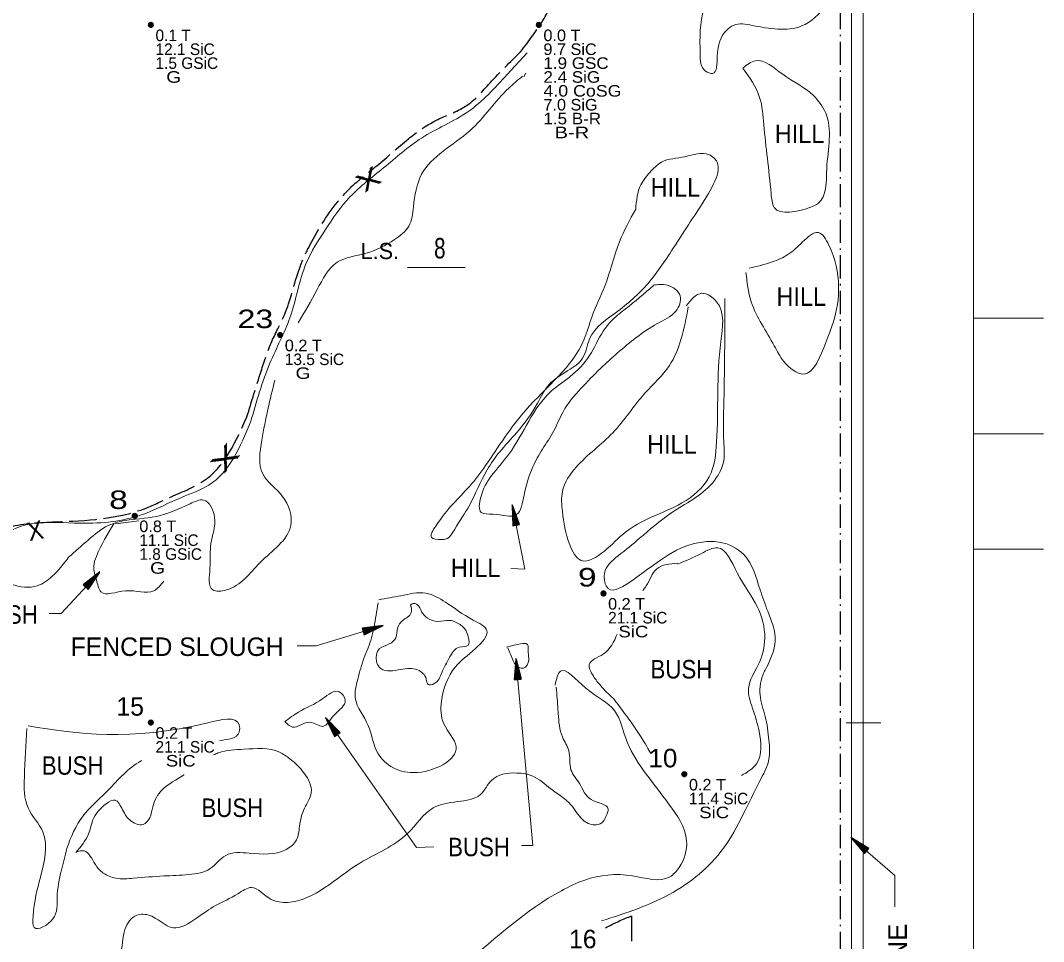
# Model space of a CAD drawing. Extents: x -496 to 480, y -450 to 700.
# Drawn here: x 37.7 to 480.3, y -94.7 to 303.7 of the extents above; entities that cross this region are included whole.
import ezdxf
from ezdxf.enums import TextEntityAlignment as Align

# ---------------------------------------------------------------- set-up
doc = ezdxf.new("R2010")
doc.units = 0
doc.header["$LTSCALE"] = 2
doc.linetypes.add('DOT_DASHED', pattern=[7.7, 5, -1.2, 0.3, -1.2])
doc.linetypes.add('LONG_DASHED', pattern=[7.5, 6, -1.5])
for name, color, linetype, lineweight in [('1', 7, 'Continuous', 13), ('2', 7, 'Continuous', 35), ('3', 7, 'Continuous', 13), ('4', 7, 'Continuous', 25)]:
    doc.layers.add(name, color=color, linetype=linetype, lineweight=lineweight)

msp = doc.modelspace()

# ---------------------------------------------------------------- linework, layer by layer
at = {"layer": '1'}
for p, q in [((205.122, 196.887), (230.122, 196.887)), ((480.331, 174.973), (449.983, 174.973)), ((480.331, 124.973), (449.983, 124.973)), ((480.331, 74.973), (449.983, 74.973)), ((394.983, -0.027), (409.983, -0.027))]:
    msp.add_line(p, q, dxfattribs=at)
for points in [[(449.983, -450.027), (449.983, 399.973), (449.983, 699.973), (-450.017, 699.973), (-450.017, 49.973), (-450.017, -450.027)], [(402.281, -402.333), (402.281, 402.339), (-402.391, 402.339)]]:
    msp.add_lwpolyline(points, dxfattribs=at)
at = {"layer": '2', "linetype": 'LONG_DASHED', "lineweight": 25}
msp.add_line((302.281, -94.495), (302.281, -83.522), dxfattribs=at)
at = {"layer": '2'}
for centre in [(94.135, 301.781), (261.975, 301.781), (150.082, 167.664), (87.142, 89.429), (289.948, 55.9), (94.135, 0.018), (324.915, -22.335)]:
    msp.add_circle(centre, 1, dxfattribs=at)
at = {"layer": '2', "linetype": 'LONG_DASHED', "lineweight": 25}
for points in [[(254.05, 290.114), (264.26, 304.622), (270.894, 317.609), (281.508, 339.607), (287.876, 356.304), (287.345, 399.506)], [(135.71, 132.34), (141.814, 151.978), (146.458, 164.864), (152.392, 177.492), (158.843, 197.594), (162.455, 205.583), (174.84, 225.169), (181.29, 232.128), (191.869, 240.89), (205.543, 252.487), (217.412, 260.477), (230.313, 266.662), (240.891, 276.713), (254.05, 290.114)], [(-121.657, 20.504), (-107.33, 29.42), (-86.423, 39.115), (-52.45, 53.658), (-20.343, 66.337), (-7.277, 69.693), (3.177, 71.184), (11.763, 72.676), (19.23, 74.913), (25.95, 80.134), (29.31, 83.117), (33.043, 84.609), (52.83, 86.846), (92.03, 92.813), (102.856, 97.66), (117.79, 105.118), (135.71, 132.34)], [(290.885, -88.682), (301.552, -83.811), (302.246, -83.558)]]:
    msp.add_spline(points, degree=3, dxfattribs=at)
at = {"layer": '2'}
for points in [[(94.124, 302.668), (94.855, 302.263), (95.006, 301.415), (94.321, 300.887), (93.512, 301.117), (93.226, 301.876), (93.473, 302.437), (94.046, 302.606), (94.72, 302.112), (94.703, 301.37), (94.186, 301.112), (93.664, 301.28), (93.439, 301.926), (94.023, 302.392), (94.461, 301.859), (94.422, 301.376), (93.793, 301.511), (93.939, 302.145), (94.231, 301.595)], [(261.964, 302.668), (262.694, 302.263), (262.846, 301.415), (262.161, 300.887), (261.352, 301.117), (261.065, 301.876), (261.313, 302.437), (261.886, 302.606), (262.56, 302.112), (262.543, 301.37), (262.026, 301.112), (261.504, 301.28), (261.279, 301.926), (261.863, 302.392), (262.301, 301.859), (262.262, 301.376), (261.633, 301.511), (261.779, 302.145), (262.071, 301.595)], [(150.071, 168.551), (150.801, 168.146), (150.953, 167.298), (150.268, 166.77), (149.459, 167), (149.172, 167.759), (149.419, 168.32), (149.992, 168.489), (150.666, 167.995), (150.65, 167.253), (150.133, 166.995), (149.61, 167.163), (149.386, 167.809), (149.97, 168.275), (150.408, 167.742), (150.369, 167.259), (149.74, 167.394), (149.886, 168.028), (150.178, 167.478)], [(87.131, 90.316), (87.861, 89.911), (88.013, 89.063), (87.328, 88.535), (86.519, 88.766), (86.232, 89.524), (86.479, 90.085), (87.052, 90.254), (87.726, 89.76), (87.71, 89.018), (87.193, 88.76), (86.67, 88.928), (86.446, 89.574), (87.03, 90.041), (87.468, 89.507), (87.429, 89.024), (86.8, 89.159), (86.946, 89.793), (87.238, 89.243)], [(289.937, 56.787), (290.668, 56.382), (290.819, 55.534), (290.134, 55.006), (289.325, 55.236), (289.039, 55.995), (289.286, 56.556), (289.859, 56.725), (290.533, 56.231), (290.516, 55.489), (289.999, 55.231), (289.477, 55.399), (289.252, 56.045), (289.836, 56.511), (290.274, 55.978), (290.235, 55.495), (289.606, 55.63), (289.752, 56.264), (290.044, 55.714)], [(94.124, 0.905), (94.855, 0.5), (95.006, -0.348), (94.321, -0.876), (93.512, -0.646), (93.226, 0.113), (93.473, 0.674), (94.046, 0.843), (94.72, 0.349), (94.703, -0.393), (94.186, -0.651), (93.664, -0.483), (93.439, 0.163), (94.023, 0.629), (94.461, 0.096), (94.422, -0.387), (93.793, -0.252), (93.939, 0.382), (94.231, -0.168)], [(324.904, -21.448), (325.634, -21.853), (325.786, -22.701), (325.101, -23.229), (324.292, -22.998), (324.005, -22.24), (324.253, -21.679), (324.826, -21.51), (325.5, -22.004), (325.483, -22.746), (324.966, -23.004), (324.444, -22.836), (324.219, -22.19), (324.803, -21.723), (325.241, -22.257), (325.202, -22.74), (324.573, -22.605), (324.719, -21.971), (325.011, -22.521)]]:
    msp.add_spline(points, degree=3, dxfattribs=at)
at = {"layer": '3', "linetype": 'DOT_DASHED', "lineweight": 25}
msp.add_line((392.281, 402.339), (392.281, -396.11), dxfattribs=at)
at = {"layer": '3'}
for p, q in [((397.281, -401.02), (397.281, 402.339)), ((248.211, 280.36), (256.977, 289.788)), ((255.491, 279.414), (256.384, 280.86)), ((78.844, 86.069), (88.946, 87.27))]:
    msp.add_line(p, q, dxfattribs=at)
for points in [[(383.644, 368.574), (387.241, 361.902), (386.213, 310.321), (375.679, 301.339), (354.355, 301.595), (346.133, 301.595), (343.307, 299.542), (339.196, 288.251), (337.141, 280.809), (334.058, 281.835), (331.746, 289.277), (333.287, 308.781), (339.453, 323.408), (346.647, 337.523), (355.383, 351.894), (368.486, 365.238), (373.367, 368.318), (382.873, 368.831)], [(350.236, 283.16), (355.682, 286.333), (367.481, 280.441), (380.642, 271.375), (386.088, 263.669), (386.541, 239.644), (382.911, 224.686), (379.28, 222.873), (363.85, 222.873), (362.489, 228.765), (359.312, 258.683), (357.497, 270.468), (350.236, 283.16)], [(137.427, 130.372), (145.648, 155.543), (154.293, 175.168), (161.366, 198.719), (169.619, 213.241), (180.229, 227.372), (194.768, 239.932), (211.273, 252.885), (231.314, 264.268), (248.211, 280.36)], [(157.893, 172.939), (166.082, 187.336), (174.727, 199.111), (187.302, 203.036), (199.484, 208.924), (205.771, 214.811), (207.736, 223.054), (211.273, 237.184), (232.1, 256.025), (248.997, 274.473), (254.892, 279.575)], [(303.887, 222.042), (306.119, 232.62), (309.971, 237.963), (315.107, 242.452), (325.164, 244.803), (335.65, 245.658), (339.074, 242.452), (337.576, 233.047), (328.374, 217.871), (321.526, 207.398)], [(321.469, 207.29), (309.982, 190.899), (296.151, 178.02), (283.96, 166.078), (280.913, 157.649), (274.583, 152.263), (266.378, 146.175), (261.455, 138.214), (252.313, 125.335), (245.045, 117.14), (239.654, 109.413), (231.918, 93.959), (225.588, 83.656), (221.837, 79.441), (219.962, 79.207), (215.508, 80.143), (217.383, 85.061), (224.885, 94.661), (231.918, 102.154), (238.95, 111.286), (256.298, 135.17), (281.616, 165.844), (284.898, 175.445), (290.524, 188.792), (296.854, 207.992), (303.887, 222.042)], [(352.959, 196.582), (362.943, 199.301), (369.75, 202.474), (376.104, 207.914), (382.911, 211.994), (387.449, 206.554), (389.264, 173.01), (386.088, 164.398), (376.557, 150.799), (367.935, 156.239), (363.85, 163.038), (353.866, 182.076), (351.597, 194.768)], [(311.388, 189.26), (317.484, 189.26), (323.11, 184.577), (321.234, 178.02), (313.264, 172.635), (304.121, 166.547), (288.649, 153.2), (280.21, 144.536), (272.473, 134.467), (268.488, 126.272), (263.565, 118.311), (259.346, 110.584), (255.595, 98.407), (252.313, 89.978), (242.232, 90.212), (237.075, 90.915), (236.841, 97.471), (241.529, 106.837), (249.031, 116.203), (267.316, 143.365), (275.521, 149.688), (283.96, 158.82), (289.821, 169.357), (296.151, 176.381), (299.433, 178.957), (311.623, 189.026)], [(325.73, 180.263), (332.537, 185.703), (338.89, 182.076), (340.706, 164.851), (338.89, 121.335), (335.714, 106.376), (323.914, 95.044), (310.3, 88.698), (299.408, 82.352), (290.332, 74.193), (280.348, 70.113), (275.356, 76.912), (272.179, 91.418), (272.179, 100.03), (278.079, 110.456), (293.962, 125.415), (308.031, 142.64), (318.469, 154.425), (323.461, 165.758), (326.637, 179.81)], [(342.51, 183.423), (341.967, 136.203), (341.967, 121.549), (341.967, 113.407), (337.076, 103.637), (319.145, 90.611), (305.56, 79.756), (296.322, 72.157), (290.345, 64.559), (291.975, 58.045), (302.843, 61.845), (332.729, 78.128), (339.793, 78.128), (350.661, 72.7), (357.725, 57.503), (360.986, 48.276), (364.246, 35.249), (360.442, 23.851), (359.355, 21.68), (357.725, 11.911), (359.899, 2.684), (361.529, -7.629), (361.529, -15.77), (358.269, -23.912), (351.205, -38.023), (343.054, -52.678), (320.231, -73.303), (289.162, -85.708)], [(58.543, 71.571), (67.055, 79.004), (75.7, 85.284), (81.988, 87.246), (96.527, 89.209), (111.067, 94.704), (116.961, 96.274), (121.677, 88.816), (120.105, 77.434), (119.712, 66.836), (120.891, 57.416), (126.786, 57.416), (141.325, 69.191), (154.686, 85.284), (151.149, 97.844), (142.504, 107.657), (142.111, 122.179), (147.765, 148.125)], [(-282.859, -78.008), (-272.887, -80.134), (-264.057, -83.662), (-249.928, -81.31), (-235.8, -71.902), (-185.173, -32.505), (-142.788, 2.187), (-109.233, 24.531), (-88.629, 34.527), (-62.138, 46.287), (-34.47, 58.047), (-7.39, 66.867), (13.803, 69.807), (24.988, 75.099), (30.874, 80.979), (65.607, 86.271), (91.509, 90.387), (107.404, 97.443), (119.177, 102.736), (137.427, 130.372)], [(99.777, 61.259), (95.348, 57.023), (83.167, 57.023), (72.557, 56.631), (70.592, 61.733), (69.413, 67.621), (70.592, 71.938), (78.058, 86.069)], [(322.126, 68.618), (332.319, 73.182), (339.349, 75.64), (347.784, 64.756), (356.572, 50.011), (359.735, 36.67), (356.923, 25.084), (352.705, 14.903), (354.463, 6.126), (357.274, -3.705), (356.22, -17.748), (349.646, -22.911)], [(-18.491, 54.826), (-14.454, 56.283), (6.738, 63.927), (20.867, 64.515), (33.818, 59.811), (45.003, 59.223), (51.478, 63.339), (58.543, 71.571)], [(307.006, 57.211), (308.418, 59.139), (312.987, 66.512), (322.126, 68.969)], [(192.778, 53.171), (202.268, 54.926), (213.164, 55.979), (221.6, 52.117), (233.55, 44.393), (239.526, 39.829), (234.605, 32.106), (225.818, 24.031), (219.842, 9.285), (220.897, -0.545), (226.169, -10.375), (207.892, -21.61), (191.723, -12.131), (188.208, -1.247), (182.584, 10.69), (183.639, 18.765), (186.451, 28.244), (189.614, 36.67), (190.669, 41.234), (192.426, 51.766)], [(206.316, 50.903), (208.035, 51.546), (209.431, 51.01), (211.257, 48.006), (213.835, 45.216), (218.346, 43.822), (223.287, 44.251), (226.831, 43.071), (230.376, 39.96), (231.45, 37.063), (231.45, 33.415), (227.583, 32.664), (223.394, 28.265), (219.957, 21.614), (216.735, 16.893), (214.05, 16.571), (213.298, 18.824), (209.538, 22.794), (202.235, 23.009), (193.642, 23.438), (191.923, 25.905), (193.105, 32.02), (197.294, 34.059), (200.086, 36.741), (200.838, 40.925), (204.168, 45.002), (206.101, 46.504), (206.961, 48.971), (206.531, 50.688)], [(294.358, 10.339), (288.734, 15.956), (285.571, 20.169), (283.813, 25.084), (289.789, 29.648), (295.888, 38.272)], [(247.989, 32.662), (252.68, 33.834), (257.077, 33.834), (257.37, 30.32), (257.663, 27.099), (255.318, 23.585), (251.507, 25.635), (250.921, 26.806), (248.575, 32.369)], [(269.001, 16.283), (271.297, 22.245), (282.315, 14.908), (294.71, 5.278), (300.22, -8.479), (308.483, -22.236), (318.124, -35.075), (325.929, -51.125), (322.715, -62.589), (318.583, -66.716), (302.515, -66.257), (281.856, -68.092), (271.756, -72.677), (229.979, -104.318), (217.583, -115.323), (209.319, -124.036), (201.974, -129.997), (187.283, -135.5), (173.51, -135.5), (164.787, -144.671), (158.36, -152.467), (154.228, -151.55), (144.587, -147.423), (132.192, -141.92), (117.042, -145.588), (110.615, -162.096), (118.878, -177.688), (120.715, -195.571), (117.96, -205.201), (111.992, -218.499), (104.646, -223.085), (95.006, -224.002), (82.61, -230.422), (72.051, -234.549), (59.196, -234.09), (48.637, -233.173), (45.883, -229.046), (46.801, -175.395), (47.26, -167.599), (55.524, -158.887), (66.542, -139.627), (70.674, -112.572), (80.315, -102.025), (82.61, -90.561), (87.201, -83.683), (93.169, -83.224), (103.728, -88.727), (113.828, -84.6), (122.092, -79.097), (131.733, -74.053), (137.701, -71.302), (145.965, -76.346), (153.31, -77.721), (184.528, -60.755), (205.188, -47.915), (216.206, -36.91), (226.765, -34.158), (236.865, -30.948), (241.456, -24.987), (252.474, -21.777), (259.36, -23.153), (267.165, -28.655), (275.888, -35.534), (280.938, -41.954), (285.988, -44.247), (289.201, -43.329), (291.038, -40.578), (291.956, -37.368), (284.61, -33.241), (279.56, -26.363), (275.888, -20.401), (274.97, -12.147), (272.215, -6.186), (270.379, 3.902), (269.92, 10.322), (269.46, 15.366)], [(152.127, 0.453), (157.99, 4.552), (168.544, 10.408), (175.58, 13.336), (178.218, 9.823), (173.234, 3.088), (168.544, -1.597), (162.974, 0.16), (155.352, -1.89), (152.127, 0.453)], [(310.473, -13.38), (308.769, -10.375), (294.358, 10.339)], [(41.026, -1.427), (118.712, -0.094), (132.327, -0.894), (132.327, -4.094), (123.81, -7.676)], [(90.271, -16.334), (88.813, -17.16), (74.664, -30.226), (64.786, -40.359), (57.845, -54.491), (55.442, -63.824), (53.573, -75.557), (51.705, -84.89), (43.696, -88.623), (43.162, -83.823), (46.366, -66.758), (47.433, -47.292), (41.026, -36.892), (39.424, -23.56), (40.492, -2.494)], [(121.24, -13.922), (123.32, -13.099), (134.487, -11.505), (149.803, -12.78), (154.27, -15.648), (160.332, -21.704), (163.523, -30.308), (160.651, -37.001), (158.418, -44.969), (157.141, -50.705), (152.674, -54.849), (136.721, -56.442), (126.51, -57.398), (119.81, -63.135), (110.557, -65.684), (99.708, -66.322), (86.627, -67.278), (78.969, -67.278), (73.545, -65.047), (70.035, -61.223), (65.249, -55.486), (62.058, -55.805)], [(61.739, -56.123), (67.163, -48.156), (69.078, -42.1), (74.821, -35.089), (78.65, -33.496), (81.521, -37.001), (85.031, -42.1), (90.774, -44.013), (93.646, -41.144), (94.922, -36.364), (99.07, -29.034), (108.323, -22.66), (108.513, -22.526)]]:
    msp.add_spline(points, degree=3, dxfattribs=at)
at = {"layer": '4', "lineweight": 13}
for points in [[(249.839, 66.649), (255.945, 66.328), (250.482, 94.256)], [(50.16, 47.27), (55.264, 47.27), (72.123, 65.19)], [(157.404, 33.248), (165.612, 33.248), (194.635, 42.032)], [(254.438, -53.133), (259.422, -53.133), (252.093, 27.684)], [(216.621, -53.718), (208.999, -54.011), (169.716, 2.209)], [(416.06, -79.63), (416.06, -66.1), (397.011, -49.61)]]:
    msp.add_lwpolyline(points, dxfattribs=at)
at = {"layer": '4'}
for points in [[(250.482, 94.256), (250.738, 85.136), (253.682, 85.712)], [(72.123, 65.19), (64.863, 59.662), (67.048, 57.607)], [(194.635, 42.032), (185.586, 40.861), (186.455, 37.989)], [(252.093, 27.684), (251.412, 18.586), (254.4, 18.857)], [(169.716, 2.209), (173.642, -6.027), (176.101, -4.309)], [(397.011, -49.61), (402.834, -56.634), (404.797, -54.366)]]:
    msp.add_lwpolyline(points, close=True, dxfattribs=at)
for points in [[(250.811, 85.225), (250.564, 93.834), (253.538, 85.808), (250.932, 85.282), (250.67, 93.292), (253.383, 85.927), (251.018, 85.43), (250.782, 92.719), (253.195, 86.038), (251.158, 85.557), (250.894, 92.065), (253.017, 86.186), (251.287, 85.748), (251.03, 91.281), (252.798, 86.292), (251.447, 85.944), (251.179, 90.436), (252.52, 86.451), (251.584, 86.169), (251.312, 89.502), (252.279, 86.668), (251.728, 86.445), (251.542, 88.407), (251.954, 86.902)], [(64.978, 59.655), (71.827, 64.877), (67.042, 57.78), (65.096, 59.59), (71.449, 64.474), (67.049, 57.974), (65.266, 59.606), (71.049, 64.049), (67.03, 58.193), (65.45, 59.566), (70.583, 63.577), (67.046, 58.423), (65.681, 59.573), (70.025, 63.009), (67.004, 58.663), (65.934, 59.558), (69.426, 62.395), (66.971, 58.982), (66.196, 59.578), (68.745, 61.742), (67.007, 59.304), (66.504, 59.622), (67.99, 60.917), (67.007, 59.705)], [(185.682, 40.797), (194.223, 41.908), (186.536, 38.143), (185.752, 40.682), (193.694, 41.748), (186.639, 38.308), (185.907, 40.611), (193.135, 41.579), (186.731, 38.507), (186.047, 40.485), (192.496, 41.402), (186.86, 38.698), (186.251, 40.376), (191.729, 41.188), (186.944, 38.927), (186.462, 40.236), (190.903, 40.955), (187.074, 39.22), (186.699, 40.123), (189.988, 40.728), (187.265, 39.481), (186.988, 40.007), (188.922, 40.389), (187.465, 39.829)], [(251.494, 18.667), (252.131, 27.256), (254.266, 18.967), (251.621, 18.712), (252.181, 26.706), (254.125, 19.101), (251.722, 18.85), (252.234, 26.124), (253.949, 19.231), (251.874, 18.961), (252.278, 25.462), (253.788, 19.397), (252.022, 19.139), (252.333, 24.668), (253.581, 19.524), (252.201, 19.317), (252.395, 23.812), (253.32, 19.711), (252.36, 19.527), (252.431, 22.87), (253.102, 19.952), (252.531, 19.787), (252.548, 21.757), (252.803, 20.218)], [(173.672, -5.916), (169.962, 1.856), (175.93, -4.279), (173.76, -5.814), (170.279, 1.403), (175.741, -4.233), (173.779, -5.645), (170.613, 0.925), (175.524, -4.207), (173.856, -5.472), (170.98, 0.372), (175.301, -4.144), (173.896, -5.245), (171.422, -0.29), (175.058, -4.136), (173.963, -5.001), (171.9, -1.002), (174.739, -4.103), (173.997, -4.74), (172.4, -1.802), (174.431, -4.002), (174.017, -4.429), (173.053, -2.71), (174.039, -3.92)], [(402.836, -56.519), (397.336, -49.892), (404.624, -54.379), (402.897, -56.399), (397.753, -50.253), (404.43, -54.381), (402.873, -56.23), (398.195, -50.635), (404.213, -54.409), (402.905, -56.044), (398.686, -51.082), (403.982, -54.402), (402.889, -55.813), (399.276, -51.616), (403.744, -54.454), (402.894, -55.561), (399.915, -52.189), (403.426, -54.5), (402.863, -55.299), (400.595, -52.842), (403.103, -54.478), (402.806, -54.993), (401.451, -53.562), (402.703, -54.494)]]:
    msp.add_lwpolyline(points, dxfattribs=at)

# ---------------------------------------------------------------- texts
at = {"layer": '1', "width": 0.75}
msp.add_text('8', height=8.89, dxfattribs=at).set_placement((219.146, 200.791), align=Align.CENTER)
at = {"layer": '1'}
msp.add_text('L.S.', height=7, dxfattribs=at).set_placement((193.216, 200.511), align=Align.CENTER)
at = {"layer": '2'}
for s, p in [('0.1 T      ', (96.135, 294.781)), ('12.1 SiC   ', (96.135, 288.781)), ('1.5 GSiC   ', (96.135, 282.781)), ('13.5 SiC   ', (152.082, 154.664)), ('11.1 SiC   ', (89.142, 76.429)), ('1.8 GSiC   ', (89.142, 70.429)), ('21.1 SiC   ', (291.948, 42.9)), ('21.1 SiC   ', (96.135, -12.982)), ('11.4 SiC   ', (326.915, -35.335))]:
    msp.add_text(s, height=5, dxfattribs=at).set_placement(p)
for s, width, p in [('0.0 T      ', 1.05, (263.975, 294.781)), ('9.7 SiC    ', 1.05, (263.975, 288.781)), ('1.9 GSC    ', 1.1, (263.975, 282.781)), ('  G        ', 1.25, (96.135, 276.781)), ('2.4 SiG    ', 1.1, (263.975, 276.781)), ('4.0 CoSG   ', 1.15, (263.975, 270.781)), ('7.0 SiG    ', 1.05, (263.975, 264.781)), ('1.5 B-R    ', 1.1, (263.975, 258.781)), ('  B-R      ', 1.3, (263.975, 252.781)), ('0.2 T      ', 1.05, (152.082, 160.664)), ('  G        ', 1.25, (152.082, 148.664)), ('0.8 T      ', 1.05, (89.142, 82.429)), ('  G        ', 1.25, (89.142, 64.429)), ('0.2 T      ', 1.05, (291.948, 48.9)), ('  SiC      ', 1.2, (291.948, 36.9)), ('0.2 T      ', 1.05, (96.135, -6.982)), ('  SiC      ', 1.2, (96.135, -18.982)), ('0.2 T      ', 1.05, (326.915, -29.335)), ('  SiC      ', 1.2, (326.915, -41.335))]:
    msp.add_text(s, height=5, dxfattribs=dict(at, width=width)).set_placement(p)
for s, width, p in [(' 23', 1.3, (147.081, 170.664)), ('  8', 1.35, (84.141, 92.429)), ('  9', 1.35, (286.948, 58.9)), (' 10', 1.05, (321.915, -19.335))]:
    msp.add_text(s, height=8, dxfattribs=dict(at, width=width)).set_placement(p, align=Align.RIGHT)
for s, p in [(' 15', (91.135, 3.018)), (' 16', (286.948, -97.57))]:
    msp.add_text(s, height=8, dxfattribs=at).set_placement(p, align=Align.RIGHT)
at = {"layer": '3'}
for rotation, width, p in [(212.084, 1.4, (186.282, 238.358)), (228.995, 1.7, (123.345, 116.917)), (11.005, 0.95, (44.933, 79.15))]:
    msp.add_text('X', height=8, rotation=rotation, dxfattribs=dict(at, width=width)).set_placement(p, align=Align.CENTER)
at = {"layer": '4'}
for s, width, p in [('HILL', 0.95, (374.776, 250.698)), ('HILL', 0.95, (321.062, 227.526)), ('HILL', 0.95, (375.503, 180.28)), ('HILL', 0.95, (319.538, 116.395)), ('HILL', 0.95, (234.635, 62.938)), ('BUSH', 0.9, (31.849, 42.765)), ('BUSH', 0.9, (323.668, 19.107)), ('BUSH', 0.9, (60.313, -22.516)), ('BUSH', 0.9, (129.401, -40.795)), ('BUSH', 0.9, (236.109, -57.778))]:
    msp.add_text(s, height=8, dxfattribs=dict(at, width=width)).set_placement(p, align=Align.CENTER)
msp.add_text('FENCED SLOUGH', height=8, dxfattribs=at).set_placement((105.515, 28.856), align=Align.CENTER)
at = {"layer": '4', "width": 1.05}
msp.add_text('FENCE LINE', height=8, rotation=90, dxfattribs=at).set_placement((421.196, -119.997), align=Align.CENTER)

doc.saveas('drawing.dxf')
